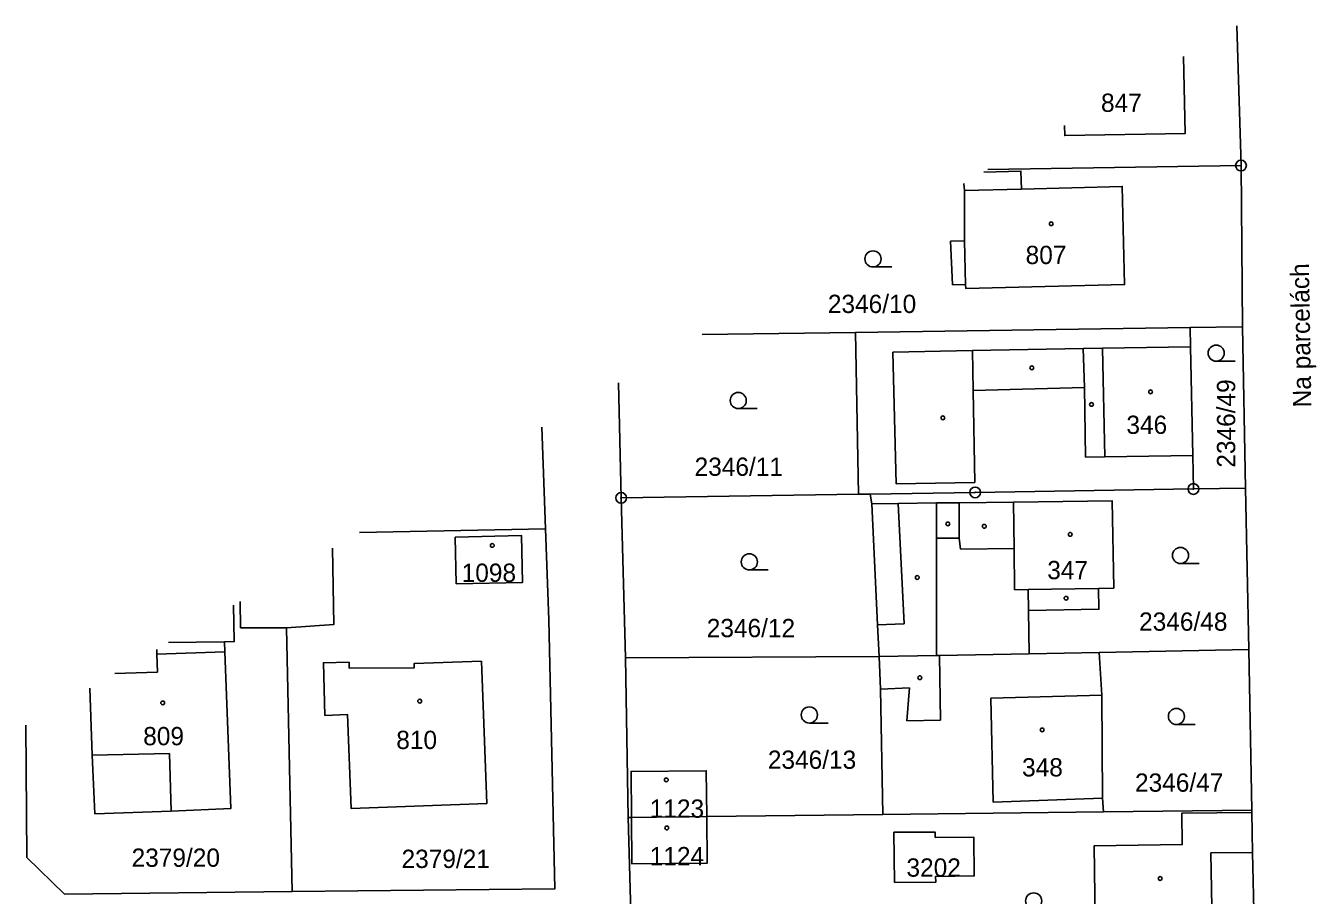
# Model space of a CAD drawing. Extents: x -758836 to -757729, y -1175316 to -1174366.
# Drawn here: x -758836.1 to -758716.1, y -1174868.1 to -1174787.2 of the extents above; entities that cross this region are included whole.
import ezdxf

# ---------------------------------------------------------------- set-up
doc = ezdxf.new("R2010")
doc.units = 0
for name, color, linetype in [('Hranice parcel', 7, 'Continuous'), ('Parcelní čísla', 7, 'Continuous'), ('Pop  PČ popisy', 7, 'Continuous'), ('Vnitřní kresba', 7, 'Continuous'), ('Značky bodu BP', 7, 'Continuous'), ('Značky budov', 7, 'Continuous'), ('Značky kultur', 7, 'Continuous')]:
    doc.layers.add(name, color=color, linetype=linetype)

msp = doc.modelspace()

# ---------------------------------------------------------------- linework, layer by layer
at = {"layer": 'Hranice parcel'}
for p, q in [((-758723.09, -1174800.23), (-758723.47, -1174787.24)), ((-758746.62, -1174800.6), (-758723.09, -1174800.23)), ((-758722.95, -1174815.23), (-758723.09, -1174800.23)), ((-758727.82, -1174815.3), (-758758.95, -1174815.75)), ((-758727.82, -1174815.3), (-758722.95, -1174815.23)), ((-758722.95, -1174815.23), (-758722.66, -1174830.22)), ((-758773.2, -1174815.95), (-758758.95, -1174815.75)), ((-758758.95, -1174815.75), (-758758.66, -1174830.78)), ((-758780.97, -1174820.44), (-758780.73, -1174831.13)), ((-758788.09, -1174824.55), (-758787.75, -1174834)), ((-758780.73, -1174831.13), (-758758.66, -1174830.78)), ((-758780.73, -1174831.13), (-758780.34, -1174845.99)), ((-758758.66, -1174830.78), (-758757.56, -1174830.77)), ((-758757.42, -1174831.68), (-758757.56, -1174830.77)), ((-758722.66, -1174830.22), (-758727.52, -1174830.3)), ((-758722.66, -1174830.22), (-758722.37, -1174845.24)), ((-758787.75, -1174834), (-758787.45, -1174842.48)), ((-758811.32, -1174867.74), (-758811.85, -1174843.2)), ((-758736.27, -1174845.5), (-758742.78, -1174845.62)), ((-758722.37, -1174845.24), (-758736.27, -1174845.5)), ((-758736.03, -1174849.48), (-758736.27, -1174845.5)), ((-758722.37, -1174845.24), (-758722.09, -1174860.16)), ((-758780.34, -1174845.99), (-758756.75, -1174845.87)), ((-758780.34, -1174845.99), (-758780.07, -1174860.85)), ((-758780.07, -1174860.85), (-758779.77, -1174860.85)), ((-758780.07, -1174860.85), (-758779.67, -1174875.98)), ((-758779.77, -1174860.85), (-758772.77, -1174860.76)), ((-758772.77, -1174860.76), (-758756.39, -1174860.57)), ((-758756.39, -1174860.57), (-758735.89, -1174860.32)), ((-758722.09, -1174860.16), (-758735.89, -1174860.32)), ((-758722.09, -1174860.37), (-758722.09, -1174860.16)), ((-758722.09, -1174860.37), (-758722.01, -1174864.11)), ((-758721.79, -1174875.22), (-758722.01, -1174864.11))]:
    msp.add_line(p, q, dxfattribs=at)
for points in [[(-758739.5, -1174796.49), (-758739.48, -1174797.44), (-758728.3, -1174797.25), (-758728.43, -1174790.1)], [(-758750.12, -1174807.25), (-758749.93, -1174811.3), (-758748.71, -1174811.32), (-758748.68, -1174811.66), (-758733.92, -1174811.29), (-758734.14, -1174802.17), (-758743.51, -1174802.41), (-758743.55, -1174800.75), (-758747.02, -1174800.83)], [(-758748.85, -1174801.89), (-758748.81, -1174802.54), (-758748.79, -1174807.23), (-758750.12, -1174807.25)], [(-758727.52, -1174830.3), (-758727.58, -1174827.19), (-758727.79, -1174817.07), (-758727.82, -1174815.3)], [(-758757.56, -1174830.77), (-758747.81, -1174830.62), (-758727.52, -1174830.3)], [(-758742.78, -1174845.62), (-758742.85, -1174841.61), (-758736.31, -1174841.49), (-758736.34, -1174839.54), (-758734.93, -1174839.51), (-758735.08, -1174831.4), (-758744.24, -1174831.52), (-758749.31, -1174831.58), (-758751.4, -1174831.6), (-758754.97, -1174831.65), (-758757.42, -1174831.68)], [(-758757.42, -1174831.68), (-758756.89, -1174842.94), (-758756.75, -1174845.87)], [(-758805.07, -1174834.35), (-758787.75, -1174834)], [(-758796.15, -1174834.77), (-758789.99, -1174834.64), (-758789.9, -1174838.99), (-758796.06, -1174839.11), (-758796.15, -1174834.77)], [(-758811.85, -1174843.2), (-758807.43, -1174842.89), (-758807.57, -1174835.79)], [(-758816.17, -1174840.76), (-758816.12, -1174843.2), (-758811.85, -1174843.2)], [(-758829.92, -1174855.05), (-758829.67, -1174860.49), (-758822.56, -1174860.27), (-758817.03, -1174860.01), (-758817.58, -1174845.43), (-758817.61, -1174844.51), (-758816.7, -1174844.49), (-758816.79, -1174841.11)], [(-758787.45, -1174842.48), (-758786.89, -1174867.47), (-758811.32, -1174867.74)], [(-758823.89, -1174845.22), (-758823.91, -1174845.67), (-758823.85, -1174847.32), (-758827.8, -1174847.47)], [(-758756.75, -1174845.87), (-758751.4, -1174845.78), (-758751.14, -1174845.77), (-758742.78, -1174845.62)], [(-758793.71, -1174846.31), (-758799.99, -1174846.54), (-758799.97, -1174846.93), (-758806.02, -1174846.96), (-758806.02, -1174846.41), (-758808.42, -1174846.46), (-758808.27, -1174851.36), (-758806.16, -1174851.28), (-758805.83, -1174860.01), (-758793.23, -1174859.55), (-758793.71, -1174846.31)], [(-758756.75, -1174845.87), (-758756.61, -1174848.91), (-758756.39, -1174860.57)], [(-758830.13, -1174848.82), (-758829.92, -1174855.05)], [(-758735.89, -1174860.32), (-758735.96, -1174859.06), (-758736.03, -1174849.48)], [(-758811.32, -1174867.74), (-758832.5, -1174867.97), (-758835.98, -1174864.56), (-758836.09, -1174852.26)], [(-758779.77, -1174860.85), (-758779.81, -1174856.56), (-758772.81, -1174856.5), (-758772.77, -1174860.76)], [(-758772.77, -1174860.76), (-758772.74, -1174865.1), (-758779.74, -1174865.15), (-758779.77, -1174860.85)], [(-758722.01, -1174864.11), (-758725.89, -1174864.14), (-758725.75, -1174872.55), (-758729.16, -1174872.6), (-758730.53, -1174873.84), (-758732.01, -1174872.64), (-758736.61, -1174872.7), (-758736.74, -1174863.47), (-758728.55, -1174863.36), (-758728.6, -1174860.45), (-758722.09, -1174860.37)], [(-758751.53, -1174862.71), (-758747.95, -1174862.66), (-758747.89, -1174866.28), (-758751.49, -1174866.32), (-758751.48, -1174866.86), (-758755.3, -1174866.88), (-758755.36, -1174862.22), (-758751.54, -1174862.21), (-758751.53, -1174862.71)]]:
    msp.add_lwpolyline(points, dxfattribs=at)
at = {"layer": 'Vnitřní kresba'}
for p, q in [((-758743.51, -1174802.41), (-758748.81, -1174802.54)), ((-758748.71, -1174811.32), (-758748.79, -1174807.23)), ((-758748.06, -1174817.44), (-758755.48, -1174817.57)), ((-758755.48, -1174817.57), (-758755.17, -1174829.83)), ((-758737.77, -1174817.25), (-758748.06, -1174817.44)), ((-758748.06, -1174817.44), (-758747.99, -1174821.13)), ((-758735.98, -1174817.22), (-758737.77, -1174817.25)), ((-758737.77, -1174817.25), (-758737.63, -1174820.86)), ((-758727.79, -1174817.07), (-758735.98, -1174817.22)), ((-758735.98, -1174817.22), (-758735.77, -1174827.3)), ((-758747.99, -1174821.13), (-758737.63, -1174820.86)), ((-758747.83, -1174829.7), (-758747.99, -1174821.13)), ((-758737.63, -1174820.86), (-758737.54, -1174827.33)), ((-758735.77, -1174827.3), (-758737.54, -1174827.33)), ((-758735.77, -1174827.3), (-758727.58, -1174827.19)), ((-758755.17, -1174829.83), (-758747.83, -1174829.7)), ((-758754.97, -1174831.65), (-758754.42, -1174842.83)), ((-758751.4, -1174831.6), (-758751.4, -1174834.88)), ((-758749.31, -1174831.58), (-758749.3, -1174834.88)), ((-758744.24, -1174831.52), (-758744.18, -1174835.85)), ((-758751.4, -1174834.88), (-758749.3, -1174834.88)), ((-758751.4, -1174834.88), (-758751.4, -1174845.78)), ((-758749.3, -1174834.88), (-758749.16, -1174835.91)), ((-758749.16, -1174835.91), (-758744.18, -1174835.85)), ((-758744.18, -1174835.85), (-758744.14, -1174839.67)), ((-758744.14, -1174839.67), (-758742.88, -1174839.65)), ((-758742.88, -1174839.65), (-758736.34, -1174839.54)), ((-758742.88, -1174839.65), (-758742.85, -1174841.61)), ((-758754.42, -1174842.83), (-758756.89, -1174842.94)), ((-758823.91, -1174845.67), (-758817.58, -1174845.43)), ((-758822.81, -1174844.59), (-758817.61, -1174844.51)), ((-758751.14, -1174845.77), (-758751.03, -1174851.8)), ((-758753.91, -1174848.79), (-758756.61, -1174848.91)), ((-758754.16, -1174851.86), (-758753.91, -1174848.79)), ((-758736.03, -1174849.48), (-758746.37, -1174849.74)), ((-758746.37, -1174849.74), (-758746.13, -1174859.43)), ((-758751.03, -1174851.8), (-758754.16, -1174851.86)), ((-758829.92, -1174855.05), (-758822.73, -1174854.91)), ((-758822.73, -1174854.91), (-758822.56, -1174860.27)), ((-758746.13, -1174859.43), (-758735.96, -1174859.06))]:
    msp.add_line(p, q, dxfattribs=at)
at = {"layer": 'Značky bodu BP'}
for centre, radius in [((-758723.09, -1174800.23), 0.5), ((-758723.09, -1174800.23), 0.0303), ((-758727.52, -1174830.3), 0.5), ((-758780.73, -1174831.13), 0.5), ((-758780.73, -1174831.13), 0.0303), ((-758747.81, -1174830.62), 0.5), ((-758747.81, -1174830.62), 0.0303), ((-758727.52, -1174830.3), 0.0303)]:
    msp.add_circle(centre, radius, dxfattribs=at)
at = {"layer": 'Značky budov'}
for centre in [(-758740.74, -1174805.64), (-758742.54, -1174819.04), (-758731.5, -1174821.27), (-758736.99, -1174822.44), (-758750.81, -1174823.69), (-758750.35, -1174833.55), (-758746.96, -1174833.77), (-758738.97, -1174834.52), (-758792.71, -1174835.55), (-758753.19, -1174838.53), (-758739.36, -1174840.46), (-758752.96, -1174847.85), (-758823.36, -1174850.19), (-758799.46, -1174850.03), (-758741.58, -1174852.7), (-758776.53, -1174857.35), (-758776.49, -1174861.82), (-758730.61, -1174866.52)]:
    msp.add_circle(centre, 0.175, dxfattribs=at)
at = {"layer": 'Značky kultur'}
for p, q in [((-758757.31, -1174809.66), (-758755.56, -1174809.66)), ((-758725.4, -1174818.42), (-758723.65, -1174818.42)), ((-758769.84, -1174822.83), (-758768.09, -1174822.83)), ((-758728.72, -1174837.23), (-758726.97, -1174837.23)), ((-758768.81, -1174837.83), (-758767.06, -1174837.83)), ((-758763.23, -1174852.06), (-758761.48, -1174852.06)), ((-758729.1, -1174852.2), (-758727.35, -1174852.2))]:
    msp.add_line(p, q, dxfattribs=at)
for centre in [(-758757.31, -1174808.91), (-758725.4, -1174817.67), (-758769.84, -1174822.08), (-758728.72, -1174836.48), (-758768.81, -1174837.08), (-758763.23, -1174851.31), (-758729.1, -1174851.45), (-758742.37, -1174868.61)]:
    msp.add_circle(centre, 0.75, dxfattribs=at)

# ---------------------------------------------------------------- texts
at = {"layer": 'Parcelní čísla'}
for s, p in [('847', (-758736.11, -1174795.24)), ('807', (-758743.12, -1174809.39)), ('2346/10', (-758761.51, -1174813.94)), ('346', (-758733.75, -1174825.18)), ('2346/11', (-758773.9, -1174829.08)), ('1098', (-758795.56, -1174838.94)), ('347', (-758741.11, -1174838.69)), ('2346/48', (-758732.57, -1174843.48)), ('2346/12', (-758772.77, -1174844.08)), ('809', (-758825.17, -1174854.13)), ('810', (-758801.64, -1174854.48)), ('2346/13', (-758767.09, -1174856.32)), ('348', (-758743.45, -1174857.03)), ('2346/47', (-758732.95, -1174858.45)), ('1123', (-758778.07, -1174860.87)), ('2379/20', (-758826.25, -1174865.43)), ('1124', (-758778.07, -1174865.29)), ('2379/21', (-758801.15, -1174865.54)), ('3202', (-758754.2, -1174866.35))]:
    msp.add_text(s, height=1.7, dxfattribs=at).set_placement(p)
msp.add_text('2346/49', height=1.7, rotation=90, dxfattribs=at).set_placement((-758723.63, -1174828.32))
at = {"layer": 'Pop  PČ popisy'}
msp.add_text('Na parcelách', height=1.7, rotation=91, dxfattribs=at).set_placement((-758716.55, -1174822.7))

doc.saveas('drawing.dxf')
